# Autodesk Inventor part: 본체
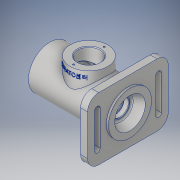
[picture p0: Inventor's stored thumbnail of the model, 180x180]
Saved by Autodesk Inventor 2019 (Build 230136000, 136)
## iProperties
Created: 2021-07
Part Number: 본체
Material: 알루미늄 6061
Document SubType Name: Modeling
Designer: jun-2-6
Mass: 729.943 g
Surface Area: 649.096 cm^2
Volume: 270.349 cm^3
Density: 2.7 g/cm^3
Appearance: 알루미늄 - 평지
Author: jun-2-6
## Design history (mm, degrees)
sketch "스케치1"
  geometry: L1 (-56, 20)-(-56, 31); L2 (-56, 31)-(-27, 31); L3 (27, 31)-(46, 31); L4 (56, 31)-(59, 31); L5 (59, 31)-(59, 22); L6 (-47, 20)-(-47, 24); L7 (-47, 24)-(-44, 24); L8 (-44, 24)-(-44, 20); L9 (-44, 20)-(-35, 20); L10 (-35, 20)-(-35, 17.5); L11 (-35, 17.5)-(-31.75, 17.5); L12 (-31.75, 17.5)-(-31.75, 18.5); L13 (-31.75, 18.5)-(-30, 18.5); L14 (-30, 18.5)-(-30, 17.5); L15 (-30, 17.5)-(-19, 17.5); L16 (-19, 17.5)-(-19, 26); L17 (-19, 26)-(19, 26); L18 (19, 26)-(19, 17.5); L19 (19, 17.5)-(30, 17.5); L20 (30, 17.5)-(30, 16); L21 (35, 10)-(37.7, 10); L22 (37.7, 10)-(37.7, 12.5); L23 (37.7, 12.5)-(44.3, 12.5); L24 (-79, 0)-(82, 0) reference; L25 (0, -6.2)-(0, 37.2) reference; L26 (45, 12.904)-(45, 16); L27 (45, 16)-(59, 22); L28 (44.3, 12.5)-(45, 12.904); L29 (-56, 20)-(-56, 0); L30 (-47, 0)-(-47, 20); L31 (30, 16)-(30, 16); L32 (30, 16)-(35, 16); L33 (35, 16)-(35, 10); L34 (-27, 31)-(27, 31); L35 (46, 31)-(56, 31); 1 further point
  constraints: 66 end point, 16 perpendicular, 10 point on line, 3 vertical, 2 horizontal, 1 collinear, 1 parallel
  dimensions: "d0" = 115 distance between parallel lines of L5 L1; "d2" = 56 distance between parallel lines of L1 L25; "d5" = 62 diameter of L2 L24; "d6" = 48 diameter of L7 L24; "d7" = 40 diameter of L9 L24; "d8" = 37 diameter of L13 L24; "d9" = 35 diameter of L15 L24; "d10" = 52 diameter of L17 L24; "d12" = 20 diameter of L21 L24; "d13" = 25 diameter of L23 L24; "d14" = 30 deg angle of L28 L23; "d15" = 32 diameter of L26.end L24; "d16" = 3 distance between parallel lines of L8 L6; "d17" = 9 distance between parallel lines of L10 L8; "d18" = 65 distance between parallel lines of L20 L10; "d19" = 9 distance between parallel lines of L1 L6; "d20" = 11 distance between parallel lines of L16 L14; "d23" = 38 distance between parallel lines of L18 L16; "d24" = 11 distance between parallel lines of L31 L18; "d25" = 1.75 distance between parallel lines of L14 L12; "d26" = 32 diameter of L32 L24; "d27" = 91 distance between parallel lines of L29 L33; "d28" = 14 distance between parallel lines of L5 L26; "d29" = 7.3 distance between parallel lines of L26 L22; "d30" = 0.7 distance from line of L26 L23.end; "d31" = 44 diameter of L5.end L24
revolve "회전1" sketch "스케치1" stored, may be unused: angle "d32" = 90 deg
node "작업 평면1"
sketch "스케치2"
  geometry: L1 (-29, 58)-(29, 58); L2 (45, 42)-(45, -42); L3 (29, -58)-(-29, -58); L4 (-45, -42)-(-45, 42); L5 (-45, 58)-(45, -58); L6 (45, 58)-(-45, -58); C1 r 31 at (0, 0); A1 r 16 centre (29, 42) between (45, 42) and (29, 58); A2 r 16 centre (-29, 42) between (-29, 58) and (-45, 42); A3 r 16 centre (-29, -42) between (-45, -42) and (-29, -58); A4 r 16 centre (29, -42) between (29, -58) and (45, -42); 1 further point
  constraints: 12 end point, 8 point on circle, 8 point on line, 8 tangent, 5 centre point, 3 equal radius, 2 midpoint, 2 parallel, 1 coincident, 1 horizontal, 1 perpendicular
  dimensions: "d34" = 116 distance between parallel lines of L3 L1; "d35" = 90 distance between parallel lines of L4 L2; "d36" = 62 diameter of C1; "d51" = 16 radius of A1
extrude "돌출1" join sketch "스케치2" distance "d37" = 10; taper "d38" = 0 deg
sketch "스케치3"
  geometry: 2 further points
  constraints: 1 coincident
hole "구멍1" sketch "스케치3" at (0, 0) diameter "d39" = 40.376; stored, may be unused: countersink angle "d43" = 90 deg, drill point angle "d45" = 118 deg; dims "d40" = 9, "d41" = 4, "d42" = 2, "d44" = 9.3
sketch "스케치4"
  geometry: L1 (-44, 25)-(-44, -25); L2 (-48, 25)-(-48, -25); L3 (-40, -25)-(-40, 25); L4 (0, -63)-(0, 63) reference; L5 (81.2, 0)-(-81.2, 0) reference; L6 (40, -25)-(40, 25); L7 (48, 25)-(48, -25); A1 r 4 centre (-44, 25) between (-40, 25) and (-48, 25); A2 r 4 centre (-44, -25) between (-48, -25) and (-40, -25); A3 r 4 centre (44, 25) between (48, 25) and (40, 25); A4 r 4 centre (44, -25) between (40, -25) and (48, -25); 2 further points
  constraints: 12 end point, 8 point on circle, 6 symmetric about line, 4 centre point, 4 tangent, 1 midpoint, 1 parallel, 1 point on line, 1 vertical, 2 other
  dimensions: "d46" = 50 distance of L1.end L1.start; "d47" = 4 radius of A1; "d48" = 44 distance between parallel lines of L4 L1
extrude "돌출2" cut sketch "스케치4" distance "d49" = 10; taper "d50" = 0 deg
node "작업 평면2"
sketch "스케치5"
  geometry: L1 (79, 0)-(-82, 0) reference; L2 (0, -81.2)-(0, 81.2) reference; C1 r 27 at (0, 0); 1 further point
  constraints: 1 centre point, 1 coincident
  dimensions: "d53" = 54 diameter of C1
extrude "돌출3" join sketch "스케치5" stored distance "d54" = 10; taper "d55" = 0 deg
sketch "스케치6"
  geometry: 2 further points
  constraints: 1 coincident
hole "구멍2" sketch "스케치6" at (0, 0) diameter "d56" = 32; stored, may be unused: countersink angle "d60" = 90 deg, drill point angle "d62" = 118 deg; dims "d57" = 9, "d58" = 4, "d59" = 2, "d61" = 30
node "작업 평면3"
sketch "스케치7"
  geometry: L1 (-27, 42)-(27, 42) reference; L2 (0, -63)-(0, 63) reference; 2 further points
  constraints: 1 point on line, 1 other
  dimensions: "d64" = 8 distance from line of L1 point (0, 34)
feature "엠보싱1" sketch "스케치7" dims "d65" = 0.5, "d66" = 0
sketch "스케치8"
  geometry: A1 r 22 centre (0, 0) between (0, 22) and (0, -22); 1 further point
  constraints: 2 point on circle, 1 centre point, 1 coincident
  dimensions: "d67" = 44 diameter of A1
hole "구멍3" sketch "스케치8" at (0, 22), (0, -22) diameter "d68" = 2.459; stored, may be unused: countersink angle "d72" = 90 deg, drill point angle "d74" = 118 deg; dims "d69" = 6, "d70" = 4, "d71" = 2, "d73" = 8
fillet "모깎기1" dims "d75" = 3
fillet "모깎기2" dims "d76" = 3
chamfer "모따기1" distance "d77" = 1; stored, may be unused: second distance "d78" = 2, angle "d79" = 45 deg
fillet "모깎기3" dims "d80" = 3
fillet "모깎기4" dims "d81" = 0.3
fillet "모깎기5" dims "d82" = 3
chamfer "모따기2" distance "d83" = 1; stored, may be unused: second distance "d84" = 2, angle "d85" = 45 deg
node "솔리드1"
other parameters: "d33" = 46, "d52" = 42, "d63" = 27
